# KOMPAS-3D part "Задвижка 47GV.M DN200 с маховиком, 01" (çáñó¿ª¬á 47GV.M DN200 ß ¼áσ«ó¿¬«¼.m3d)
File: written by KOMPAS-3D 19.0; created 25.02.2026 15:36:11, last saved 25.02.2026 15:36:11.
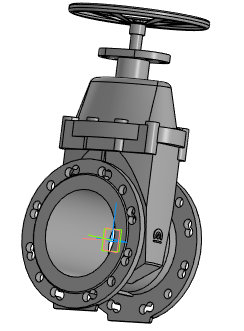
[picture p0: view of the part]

Document properties: Автор: Энергия; Полное имя файла: ..\..\47GVM\DR.47GVM.200.16.00.000\DR.47GVM.200.16.00.00 - Задвижка с обрезиненным клином DN200.a3d

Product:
- Part/product: Задвижка 47GV.M DN200 с маховиком  | designation 01
    Масса: 49.1505
  - Component [detail]: Корпус DN200  | pos. 3  | Материал: ВЧ50 ГОСТ 7293-85 (density 7200 kg/m3); Масса: 29.8323; Раздел спецификации: Детали; Форматы листов документа: 3xA3; source file: 47GV.M DN200\DR.47GVM.200.16.00.001 - Корпус.cdw, 47GV.M DN200\DR.47GVM.200.16.00.001 - Корпус.m3d
  - Component [detail]: Крышка DN200  | pos. 4  | Материал: ВЧ50 ГОСТ 7293-85 (density 7200 kg/m3); Масса: 8.49311; Раздел спецификации: Детали; Форматы листов документа: 2xA3; source file: 47GV.M DN200\DR.47GVM.200.16.00.002 - Крышка.cdw, 47GV.M DN200\DR.47GVM.200.16.00.002 - Крышка.m3d
  - Component [detail]: Шпиндель  | pos. 5  | Материал: Сталь 20Х13 ГОСТ 5632 - 2014 (density 7670 kg/m3); Масса: 1.57176; Раздел спецификации: Детали; Форматы листов документа: A3; source file: 47GV.M DN200\DR.47GVM.200.16.00.003 - Шпиндель.cdw, 47GV.M DN200\DR.47GVM.200.16.00.003 - Шпиндель.m3d
  - Component [assembly]: Клин с направляющими  | designation DR.47GVM.200.16.01.000  | pos. 2  | Масса: 7.86529; Раздел спецификации: Сборочные единицы; Форматы листов документа: A4; source file: 47GV.M DN200\DR.47GVM.200.16.01.000 - Клин с направляющими.a3d, 47GV.M DN200\DR.47GVM.200.16.01.000 - Клин с направляющими.spw, 47GV.M DN200\DR.47GVM.200.16.01.000 СБ - Клин с направляющими.cdw
  - Component [detail]: Маховик 320  | pos. 21  | Масса: 0.78922; Раздел спецификации: Прочие изделия; source file: 47GV.M DN200\Маховик 320.m3d
  - Component [standard]: Шайба1021695878  | pos. 22  | Материал: Сталь 12Х18Н10Т ГОСТ 5632-2014 (density 1000 kg/m3); Масса: 0.0121728; Раздел спецификации: Стандартные изделия; Рассекать на разрезах: no; additional columns: ГОСТ 6958-78; A 10.21
  - Component [standard]: Болт106g207798  | pos. 12  | Масса: 0.02379; Раздел спецификации: Стандартные изделия; Рассекать на разрезах: no; additional columns: ГОСТ 7798-70; М10-6gx20
  - Component [standard]: Кольцо A50.50 ХГА ГОСТ 13943-86  | pos. 48  | Материал: Сталь 50 ХГА ГОСТ 14959-2016 (density 1000 kg/m3); Масса: 0.0068; Раздел спецификации: Стандартные изделия; Рассекать на разрезах: no
- Part/product: Задвижка 47GV.M DN200 с маховиком
    Масса: 90.1088
    source file: 47GV.M DN200\DR.47GVM.200.16.00.00 - Задвижка с обрезиненным клином DN200.spw
  - Component: Задвижка с обрезиненным клином DN200. Сборочный чертеж  | designation DR.47GVM.200.16.00.00СБ  | pos. 0  | Масса: 49.2062; Раздел спецификации: Документация; Форматы листов документа: 2xA3; source file: 47GV.M DN200\DR.47GVM.200.16.00.000 СБ - Задвижка с обрезиненным клином DN200.cdw

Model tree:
1. Операция без истории:1

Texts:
  Точка начала. Х
  Точка начала. Y
  Точка начала. Z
